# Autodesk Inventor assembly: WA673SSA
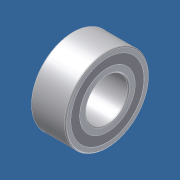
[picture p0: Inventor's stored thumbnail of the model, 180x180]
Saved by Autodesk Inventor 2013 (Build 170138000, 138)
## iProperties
Category: PARTsolutions
Created: 2011-07
Part Number: WA673SSA
Catalog Web Link: www.cadenas.de
Description: With double shield ZZ -
Document SubType Name: Assembly
Designer: PARTsolutions
NB: WA673SSA
NN: With double shield ZZ
NBSYN: $ORDER.
LINA: WA673SSA
PSOL_MULTISOLIDPART: 0.0
SD: 3.0
D: 6
B: 2.0
B1: 2.5
D1: 7.2
D2: 7.2
C1: 0.6
C2: 0.6
R: 0.08
ORDER: WA673SSA
CR: 242
COR: 94
CRF: 25
CORF: 9,5
LSG: 60 000
LSO: 71 000
MASS: 0.20
ORDER1: 673
WSS: WA673SSA
WDS: SSA
UTWF: FL673
FORSS: FLWA673SA
FORDS: SSA
DA1: 3,6
DA2: 4,1
DA: 5,4
RAS: 0,08
MASS1: 0.26
VERS: 3
X: 1.500
N: 9
O: 14.130
RB: 0.444
PPATH: mss_asmtpl.prj
KT: DUMMY
CreationOption_UseAsmMates: 0
SUPPLIER: NTN
ARTICLENO: WA673SSA
BOMINFO: WA673SSA
CREATOR: CADENAS GmbH
PSOL_IDENT_0: {\\10.0.0.251\ps_data\23d-libs\ntn\ball_roller_bearings\miniature_extra_small_bb\metric_system_sizes
PSOL_IDENT_1: \mss_zz_asmtab.prj},181 {VTYP=3D},{STYP=ASSTAB},{NB=WA673SSA},{LINA=WA673SSA},{NN=With double shield
PSOL_IDENT_2: ZZ},{DATE=11.12.2007 08:48:24},{GEOMDATE=17.04.2007},{VERSION=},{LINEID=12590},{LINESUBID=-1},{WBVA
PSOL_IDENT_3: R=}  {NB=WA673SSA},{LINA=WA673SSA},{KT=DUMMY},{IDNR=},{SD=3.0},{D=6},{B=2.0},{B1=2.5},{D1=7.2},{D2=7
PSOL_IDENT_4: .2},{C1=0.6},{C2=0.6},{R=0.08},{ORDER=WA673SSA},{CR=242},{COR=94},{CRF=25},{CORF=9,5},{LSG=60 000},{
PSOL_IDENT_5: LSO=71 000},{MASS=0.20},{ORDER1=673},{WSS=WA673SSA},{WDS=SSA},{UTWF=FL673},{FORSS=FLWA673SA},{FORDS=
PSOL_IDENT_6: SSA},{DA1=3,6},{DA2=4,1},{DA=5,4},{RAS=0,08},{MASS1=0.26},{VERS=3},{X=1.5},{N=9},{O=14.13},{RB=0.444
PSOL_IDENT_7: },{PPATH=mss_asmtpl.prj}
Title: WA673SSA
Author: Cadenas PARTsolutions
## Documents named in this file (5)
- D:\_an13-14\FORMULAIRE_2014\Sujet E4 Poissy 2014\Modélisation_7970_shimano_2014\éléments standards\PARTserver35515621\WA673SSA.iam
- D:\_an13-14\FORMULAIRE_2014\Sujet E4 Poissy 2014\Modélisation_7970_shimano_2014\éléments standards\PARTserver35515621\WA673SSA_Inner_ring.ipt
- D:\_an13-14\FORMULAIRE_2014\Sujet E4 Poissy 2014\Modélisation_7970_shimano_2014\éléments standards\PARTserver35515621\WA673SSA_Outer_ring.ipt
- D:\_an13-14\FORMULAIRE_2014\Sujet E4 Poissy 2014\Modélisation_7970_shimano_2014\éléments standards\PARTserver35515621\WA673SSA_Shield.ipt
- D:\_an13-14\FORMULAIRE_2014\Sujet E4 Poissy 2014\Modélisation_7970_shimano_2014\éléments standards\PARTserver35515621\WA673SSA_Ball.ipt
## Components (13 placed, 4 different names)
1. WA673SSA Inner ring:1
2. WA673SSA Outer ring:1
3. WA673SSA Shield:1
4. WA673SSA Shield:2
5. WA673SSA Ball:1
6. WA673SSA Ball:2
7. WA673SSA Ball:3
8. WA673SSA Ball:4
9. WA673SSA Ball:5
10. WA673SSA Ball:6
11. WA673SSA Ball:7
12. WA673SSA Ball:8
13. WA673SSA Ball:9
